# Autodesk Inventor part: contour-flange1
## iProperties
Author: Administrator
Created: 2000-12
Part Number: contour-flange1
Material: Aluminum
Document SubType Name: Sheet Metal
Designer: Administrator
Control State: 0
Master: False
Checked Out: False
PropertySet Name: Design Tracking Control
Shininess: 25.0
PropertySet Name: _Private Model Information
Density: 0.0
Volumn: 0.0
Area: 0.0
PropertySet Name: Model Information
